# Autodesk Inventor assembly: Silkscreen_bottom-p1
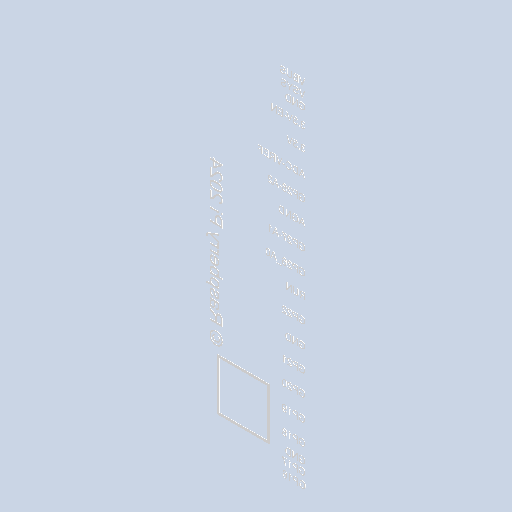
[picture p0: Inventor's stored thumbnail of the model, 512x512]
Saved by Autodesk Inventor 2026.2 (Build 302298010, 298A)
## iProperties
Created: 2026-10
Part Number: Silkscreen_bottom-p1
Document SubType Name: Assembly
Designer: mel
Author: mel
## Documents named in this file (23)
- D:\travail\année 2026-2027\1 sti2d IT\poubelle à verre\raspberry-pico-2-microcontroller-rp2350-1.snapshot.5\raspberry_pico_2\raspberry_pico_2\Silkscreen_bottom-p1.iam
- D:\travail\année 2026-2027\1 sti2d IT\poubelle à verre\raspberry-pico-2-microcontroller-rp2350-1.snapshot.5\raspberry_pico_2\raspberry_pico_2\text_raspberry.ipt
- D:\travail\année 2026-2027\1 sti2d IT\poubelle à verre\raspberry-pico-2-microcontroller-rp2350-1.snapshot.5\raspberry_pico_2\raspberry_pico_2\Text_vbus.ipt
- D:\travail\année 2026-2027\1 sti2d IT\poubelle à verre\raspberry-pico-2-microcontroller-rp2350-1.snapshot.5\raspberry_pico_2\raspberry_pico_2\Text_vsys.ipt
- D:\travail\année 2026-2027\1 sti2d IT\poubelle à verre\raspberry-pico-2-microcontroller-rp2350-1.snapshot.5\raspberry_pico_2\raspberry_pico_2\Text_gnd001.ipt
- D:\travail\année 2026-2027\1 sti2d IT\poubelle à verre\raspberry-pico-2-microcontroller-rp2350-1.snapshot.5\raspberry_pico_2\raspberry_pico_2\Text_3.3v-en.ipt
- D:\travail\année 2026-2027\1 sti2d IT\poubelle à verre\raspberry-pico-2-microcontroller-rp2350-1.snapshot.5\raspberry_pico_2\raspberry_pico_2\Text_3.3V.ipt
- D:\travail\année 2026-2027\1 sti2d IT\poubelle à verre\raspberry-pico-2-microcontroller-rp2350-1.snapshot.5\raspberry_pico_2\raspberry_pico_2\Text_ADC-VREF.ipt
- D:\travail\année 2026-2027\1 sti2d IT\poubelle à verre\raspberry-pico-2-microcontroller-rp2350-1.snapshot.5\raspberry_pico_2\raspberry_pico_2\Text_GP28-A2.ipt
- D:\travail\année 2026-2027\1 sti2d IT\poubelle à verre\raspberry-pico-2-microcontroller-rp2350-1.snapshot.5\raspberry_pico_2\raspberry_pico_2\Text_AGND.ipt
- D:\travail\année 2026-2027\1 sti2d IT\poubelle à verre\raspberry-pico-2-microcontroller-rp2350-1.snapshot.5\raspberry_pico_2\raspberry_pico_2\Text_GP27-A1.ipt
- D:\travail\année 2026-2027\1 sti2d IT\poubelle à verre\raspberry-pico-2-microcontroller-rp2350-1.snapshot.5\raspberry_pico_2\raspberry_pico_2\Text_GP26_A0.ipt
- D:\travail\année 2026-2027\1 sti2d IT\poubelle à verre\raspberry-pico-2-microcontroller-rp2350-1.snapshot.5\raspberry_pico_2\raspberry_pico_2\Text_RUN.ipt
- D:\travail\année 2026-2027\1 sti2d IT\poubelle à verre\raspberry-pico-2-microcontroller-rp2350-1.snapshot.5\raspberry_pico_2\raspberry_pico_2\Text_GP22.ipt
- D:\travail\année 2026-2027\1 sti2d IT\poubelle à verre\raspberry-pico-2-microcontroller-rp2350-1.snapshot.5\raspberry_pico_2\raspberry_pico_2\Text_GND002.ipt
- D:\travail\année 2026-2027\1 sti2d IT\poubelle à verre\raspberry-pico-2-microcontroller-rp2350-1.snapshot.5\raspberry_pico_2\raspberry_pico_2\Text_GP21.ipt
- D:\travail\année 2026-2027\1 sti2d IT\poubelle à verre\raspberry-pico-2-microcontroller-rp2350-1.snapshot.5\raspberry_pico_2\raspberry_pico_2\Text_GP20.ipt
- D:\travail\année 2026-2027\1 sti2d IT\poubelle à verre\raspberry-pico-2-microcontroller-rp2350-1.snapshot.5\raspberry_pico_2\raspberry_pico_2\Text_GP19.ipt
- D:\travail\année 2026-2027\1 sti2d IT\poubelle à verre\raspberry-pico-2-microcontroller-rp2350-1.snapshot.5\raspberry_pico_2\raspberry_pico_2\Text_GP18.ipt
- D:\travail\année 2026-2027\1 sti2d IT\poubelle à verre\raspberry-pico-2-microcontroller-rp2350-1.snapshot.5\raspberry_pico_2\raspberry_pico_2\Text_GND.ipt
- D:\travail\année 2026-2027\1 sti2d IT\poubelle à verre\raspberry-pico-2-microcontroller-rp2350-1.snapshot.5\raspberry_pico_2\raspberry_pico_2\Text_GP17.ipt
- D:\travail\année 2026-2027\1 sti2d IT\poubelle à verre\raspberry-pico-2-microcontroller-rp2350-1.snapshot.5\raspberry_pico_2\raspberry_pico_2\Text_GP16.ipt
- D:\travail\année 2026-2027\1 sti2d IT\poubelle à verre\raspberry-pico-2-microcontroller-rp2350-1.snapshot.5\raspberry_pico_2\raspberry_pico_2\Body007.ipt
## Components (22 placed, 22 different names)
1. 2791
2. 2792
3. 2793
4. 2794
5. 2795
6. 2796
7. 2797
8. 2798
9. 2799
10. 2800
11. 2801
12. 2802
13. 2803
14. 2804
15. 2805
16. 2806
17. 2807
18. 2808
19. 2809
20. 2810
21. 2811
22. 2812
